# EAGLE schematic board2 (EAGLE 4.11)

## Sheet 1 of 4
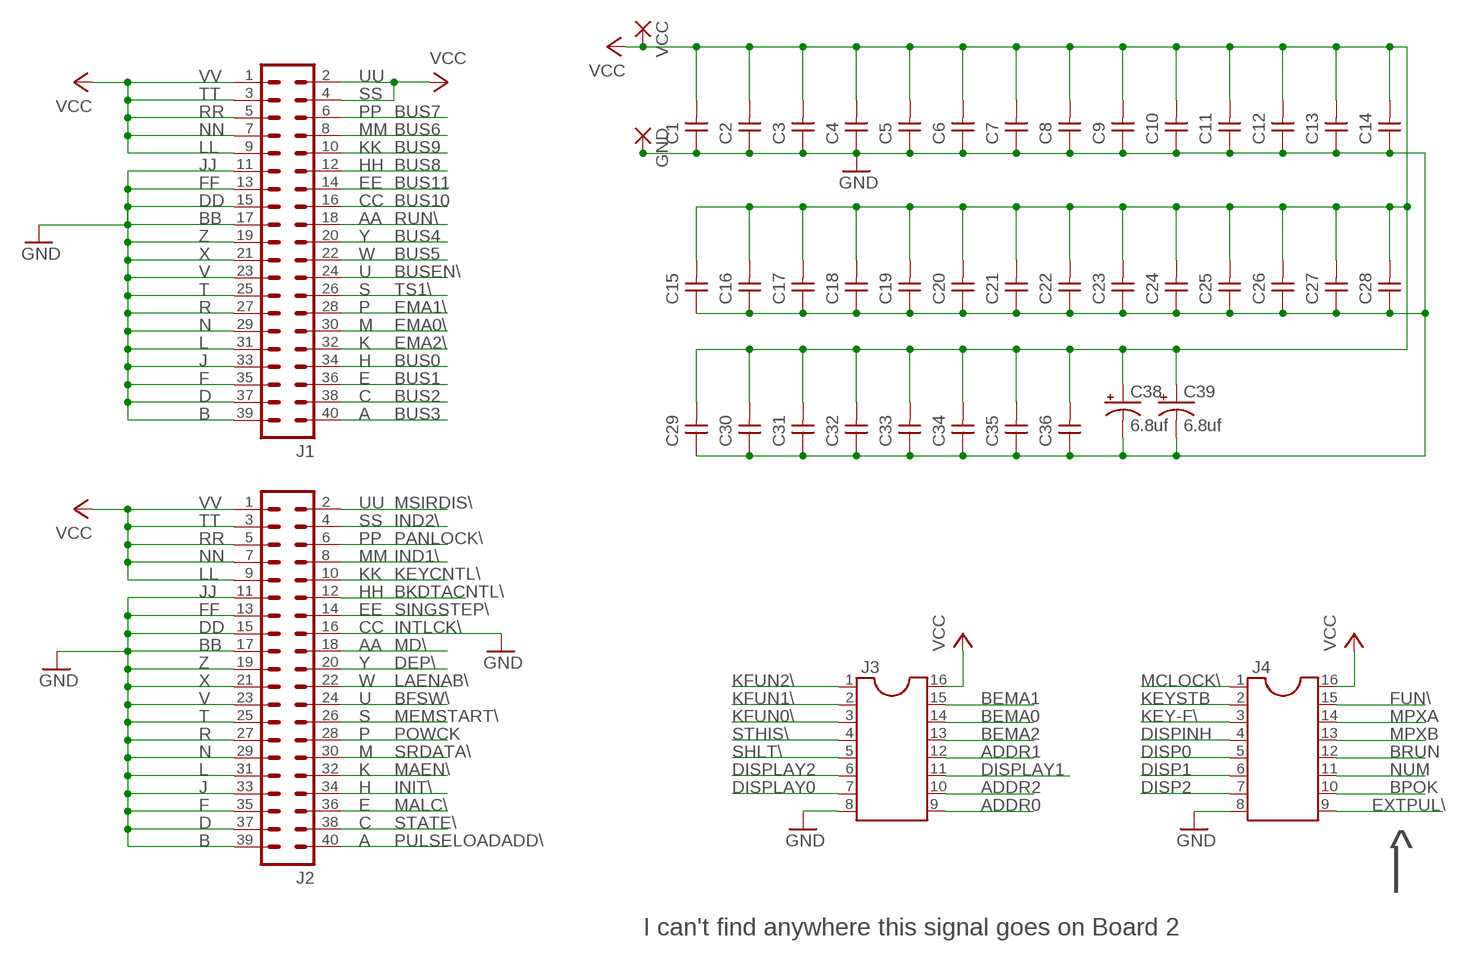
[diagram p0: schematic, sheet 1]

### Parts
C1  CAPNP-5  [C-5]
C2  CAPNP-5  [C-5]
C3  CAPNP-5  [C-5]
C4  CAPNP-5  [C-5]
C5  CAPNP-5  [C-5]
C6  CAPNP-5  [C-5]
C7  CAPNP-5  [C-5]
C8  CAPNP-5  [C-5]
C9  CAPNP-5  [C-5]
C10  CAPNP-5  [C-5]
C11  CAPNP-5  [C-5]
C12  CAPNP-5  [C-5]
C13  CAPNP-5  [C-5]
C14  CAPNP-5  [C-5]
C15  CAPNP-5  [C-5]
C16  CAPNP-5  [C-5]
C17  CAPNP-5  [C-5]
C18  CAPNP-5  [C-5]
C19  CAPNP-5  [C-5]
C20  CAPNP-5  [C-5]
C21  CAPNP-5  [C-5]
C22  CAPNP-5  [C-5]
C23  CAPNP-5  [C-5]
C24  CAPNP-5  [C-5]
C25  CAPNP-5  [C-5]
C26  CAPNP-5  [C-5]
C27  CAPNP-5  [C-5]
C28  CAPNP-5  [C-5]
C29  CAPNP-5  [C-5]
C30  CAPNP-5  [C-5]
C31  CAPNP-5  [C-5]
C32  CAPNP-5  [C-5]
C33  CAPNP-5  [C-5]
C34  CAPNP-5  [C-5]
C35  CAPNP-5  [C-5]
C36  CAPNP-5  [C-5]
C38  6.8uf  CPOL-USE15-5AXIAL  [E15-5]
C39  6.8uf  CPOL-USE15-5AXIAL  [E15-5]
GND  3,81/1,4  [3,81/1,4]
J1  40H  [40H]
J2  40H  [40H]
J3  DIL16S  [SOCKED-16]
J4  DIL16S  [SOCKED-16]
VCC  3,81/1,4  [3,81/1,4]

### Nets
ADDR0: J3.9 ; also sheet 2
ADDR1: J3.12 ; also sheet 2
ADDR2: J3.10 ; also sheet 2
BEMA0: J3.14 ; also sheet 4
BEMA1: J3.15 ; also sheet 4
BEMA2: J3.13 ; also sheet 4
BFSW\: J2.24 ; also sheet 4
BKDTACNTL\: J2.12 ; also sheet 4
BPOK: J4.10 ; also sheet 2,3,4
BRUN: J4.12 ; also sheet 3,4
BUS0: J1.34 ; also sheet 2
BUS1: J1.36 ; also sheet 2
BUS2: J1.38 ; also sheet 2
BUS3: J1.40 ; also sheet 2
BUS4: J1.20 ; also sheet 2
BUS5: J1.22 ; also sheet 2
BUS6: J1.8 ; also sheet 2
BUS7: J1.6 ; also sheet 2
BUS8: J1.12 ; also sheet 2
BUS9: J1.10 ; also sheet 2
BUS10: J1.16 ; also sheet 2
BUS11: J1.14 ; also sheet 2
BUSEN\: J1.24 ; also sheet 4
DEP\: J2.20 ; also sheet 4
DISP0: J4.5 ; also sheet 4
DISP1: J4.6 ; also sheet 4
DISP2: J4.7 ; also sheet 4
DISPINH: J4.4 ; also sheet 3,4
DISPLAY0: J3.7 ; also sheet 2
DISPLAY1: J3.11 ; also sheet 2
DISPLAY2: J3.6 ; also sheet 2
EMA0\: J1.30 ; also sheet 4
EMA1\: J1.28 ; also sheet 4
EMA2\: J1.32 ; also sheet 4
EXTPUL\: J4.9
FUN\: J4.15 ; also sheet 3,4
GND [Supply]: C1.1 C2.1 C3.1 C4.1 C5.1 C6.1 C7.1 C8.1 C9.1 C10.1 C11.1 C12.1 C13.1 C14.1 C15.1 C16.1 C17.1 C18.1 C19.1 C20.1 C21.1 C22.1 C23.1 C24.1 C25.1 C26.1 C27.1 C28.1 C29.1 C30.1 C31.1 C32.1 C33.1 C34.1 C35.1 C36.1 C38.- C39.- GND.1(P) J1.11 J1.13 J1.15 J1.17 J1.19 J1.21 J1.23 J1.25 J1.27 J1.29 J1.31 J1.33 J1.35 J1.37 J1.39 J2.11 J2.13 J2.15 J2.16 J2.17 J2.19 J2.21 J2.23 J2.25 J2.27 J2.29 J2.31 J2.33 J2.35 J2.37 J2.39 J3.8 J4.8 ; also sheet 2,3,4
IND1\: J2.8 ; also sheet 4
IND2\: J2.4 ; also sheet 4
INIT\: J2.34 ; also sheet 4
KEY-F\: J4.3 ; also sheet 4
KEYCNTL\: J2.10 ; also sheet 4
KEYSTB: J4.2 ; also sheet 3
KFUN0\: J3.3 ; also sheet 2,4
KFUN1\: J3.2 ; also sheet 2,4
KFUN2\: J3.1 ; also sheet 2,4
LAENAB\: J2.22 ; also sheet 4
MAEN\: J2.32 ; also sheet 4
MALC\: J2.36 ; also sheet 4
MCLOCK\: J4.1 ; also sheet 3
MD\: J2.18 ; also sheet 4
MEMSTART\: J2.26 ; also sheet 4
MPXA: J4.14 ; also sheet 2
MPXB: J4.13 ; also sheet 2
MSIRDIS\: J2.2 ; also sheet 4
NUM: J4.11 ; also sheet 3
PANLOCK\: J2.6 ; also sheet 4
POWCK: J2.28 ; also sheet 4
PULSELOADADD\: J2.40 ; also sheet 4
RUN\: J1.18 ; also sheet 3
SHLT\: J3.5 ; also sheet 4
SINGSTEP\: J2.14 ; also sheet 4
SRDATA\: J2.30 ; also sheet 3,4
STATE\: J2.38 ; also sheet 4
STHIS\: J3.4 ; also sheet 4
TS1\: J1.26 ; also sheet 3,4
VCC [Supply]: C1.2 C2.2 C3.2 C4.2 C5.2 C6.2 C7.2 C8.2 C9.2 C10.2 C11.2 C12.2 C13.2 C14.2 C15.2 C16.2 C17.2 C18.2 C19.2 C20.2 C21.2 C22.2 C23.2 C24.2 C25.2 C26.2 C27.2 C28.2 C29.2 C30.2 C31.2 C32.2 C33.2 C34.2 C35.2 C36.2 C38.+ C39.+ J1.1 J1.2 J1.3 J1.4 J1.5 J1.7 J1.9 J2.1 J2.3 J2.5 J2.7 J2.9 J3.16 J4.16 VCC.1(P) ; also sheet 2,3,4

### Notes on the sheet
- VV | UU
- TT | SS
- RR | PP
- NN | MM
- LL | KK
- JJ | HH
- FF | EE
- DD | CC
- BB | AA
- Z | Y
- X | W
- V | U
- T | S
- R | P
- N | M
- L | K
- J | H
- F | E
- D | C
- B | A
- VV | UU
- TT | SS
- RR | PP
- NN | MM
- LL | KK
- JJ | HH
- FF | EE
- DD | CC | INTLCK\
- BB | AA
- Z | Y
- X | W
- V | U
- T | S
- R | P
- N | M
- L | K
- J | H
- F | E
- D | C
- B | A
- ^
- |
- I can't find anywhere this signal goes on Board 2

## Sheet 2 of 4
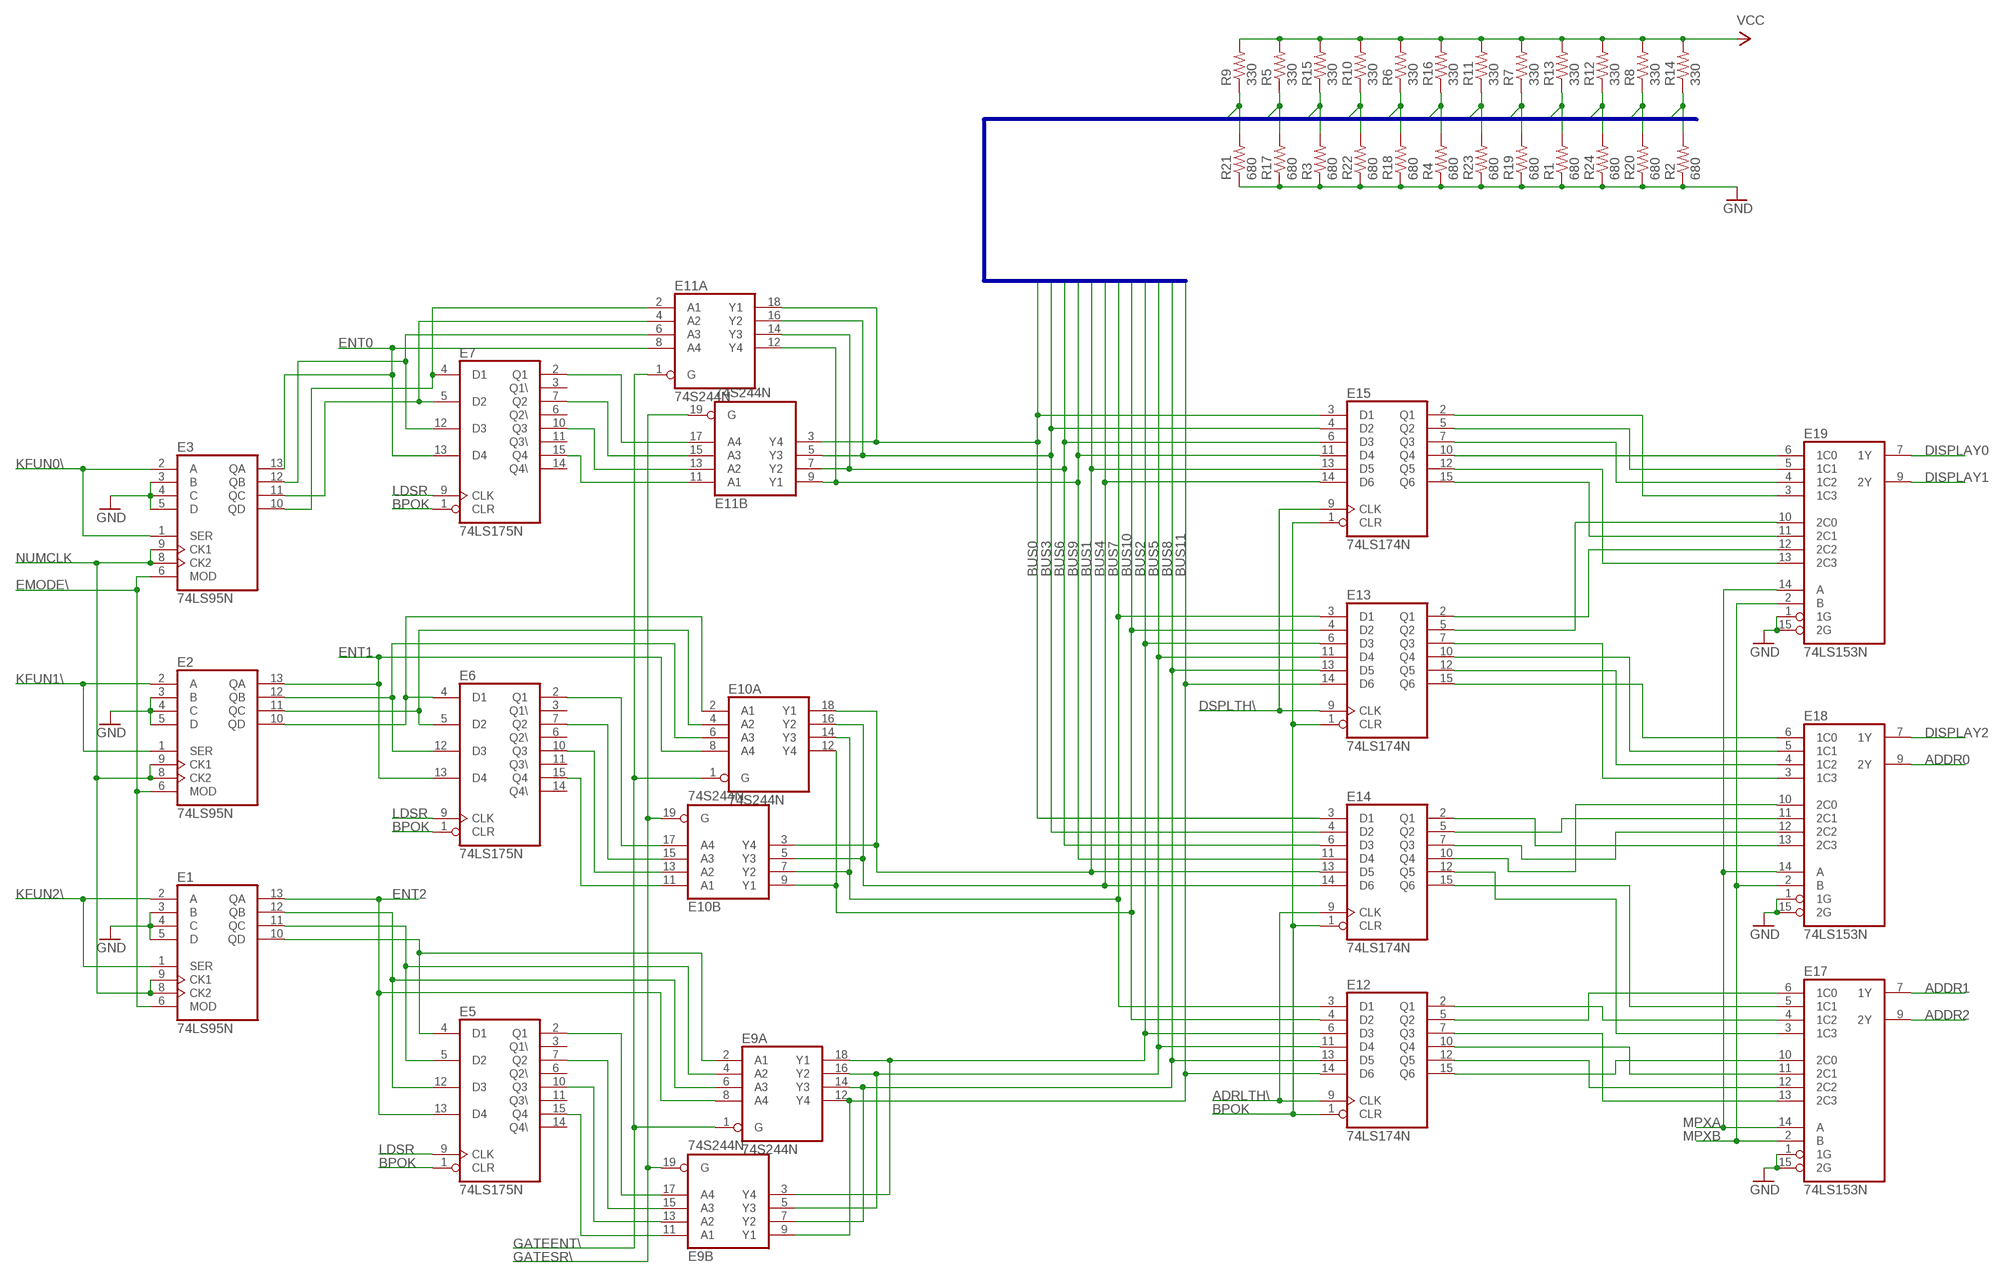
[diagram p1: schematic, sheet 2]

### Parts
E1  74LS95N  [DIL14]
E2  74LS95N  [DIL14]
E3  74LS95N  [DIL14]
E5  74LS175N  [DIL16]
E6  74LS175N  [DIL16]
E7  74LS175N  [DIL16]
E9  74S244N  [DIL20]
E10  74S244N  [DIL20]
E11  74S244N  [DIL20]
E12  74LS174N  [DIL16]
E13  74LS174N  [DIL16]
E14  74LS174N  [DIL16]
E15  74LS174N  [DIL16]
E17  74LS153N  [DIL16]
E18  74LS153N  [DIL16]
E19  74LS153N  [DIL16]
R1  680  R-US_0207/10  [0207/10]
R2  680  R-US_0207/10  [0207/10]
R3  680  R-US_0207/10  [0207/10]
R4  680  R-US_0207/10  [0207/10]
R5  330  R-US_0207/10  [0207/10]
R6  330  R-US_0207/10  [0207/10]
R7  330  R-US_0207/10  [0207/10]
R8  330  R-US_0207/10  [0207/10]
R9  330  R-US_0207/10  [0207/10]
R10  330  R-US_0207/10  [0207/10]
R11  330  R-US_0207/10  [0207/10]
R12  330  R-US_0207/10  [0207/10]
R13  330  R-US_0207/10  [0207/10]
R14  330  R-US_0207/10  [0207/10]
R15  330  R-US_0207/10  [0207/10]
R16  330  R-US_0207/10  [0207/10]
R17  680  R-US_0207/10  [0207/10]
R18  680  R-US_0207/10  [0207/10]
R19  680  R-US_0207/10  [0207/10]
R20  680  R-US_0207/10  [0207/10]
R21  680  R-US_0207/10  [0207/10]
R22  680  R-US_0207/10  [0207/10]
R23  680  R-US_0207/10  [0207/10]
R24  680  R-US_0207/10  [0207/10]

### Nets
ADDR0: E18.9(2Y) ; also sheet 1
ADDR1: E17.7(1Y) ; also sheet 1
ADDR2: E17.9(2Y) ; also sheet 1
ADRLTH\: E12.9(CLK) E14.9(CLK) ; also sheet 3
BPOK: E5.1(CLR) E6.1(CLR) E7.1(CLR) E12.1(CLR) E13.1(CLR) E14.1(CLR) E15.1(CLR) ; also sheet 1,3,4
BUS0: E11.3(B:Y4) E11.18(A:Y1) E14.3(D1) E15.3(D1) R9.1 R21.2 ; also sheet 1
BUS1: E10.3(B:Y4) E10.18(A:Y1) E14.13(D5) E15.13(D5) R5.1 R17.2 ; also sheet 1
BUS2: E9.3(B:Y4) E9.18(A:Y1) E12.6(D3) E13.6(D3) R3.2 R15.1 ; also sheet 1
BUS3: E11.5(B:Y3) E11.16(A:Y2) E14.4(D2) E15.4(D2) R10.1 R22.2 ; also sheet 1
BUS4: E10.5(B:Y3) E10.16(A:Y2) E14.14(D6) E15.14(D6) R6.1 R18.2 ; also sheet 1
BUS5: E9.5(B:Y3) E9.16(A:Y2) E12.11(D4) E13.11(D4) R4.2 R16.1 ; also sheet 1
BUS6: E11.7(B:Y2) E11.14(A:Y3) E14.6(D3) E15.6(D3) R11.1 R23.2 ; also sheet 1
BUS7: E10.7(B:Y2) E10.14(A:Y3) E12.3(D1) E13.3(D1) R7.1 R19.2 ; also sheet 1
BUS8: E9.7(B:Y2) E9.14(A:Y3) E12.13(D5) E13.13(D5) R1.2 R12.1 R13.1 R24.2 ; also sheet 1
BUS9: E11.9(B:Y1) E11.12(A:Y4) E14.11(D4) E15.11(D4) ; also sheet 1
BUS10: E10.9(B:Y1) E10.12(A:Y4) E12.4(D2) E13.4(D2) R8.1 R20.2 ; also sheet 1
BUS11: E9.9(B:Y1) E9.12(A:Y4) E12.14(D6) E13.14(D6) R2.2 R14.1 ; also sheet 1
DISPLAY0: E19.7(1Y) ; also sheet 1
DISPLAY1: E19.9(2Y) ; also sheet 1
DISPLAY2: E18.7(1Y) ; also sheet 1
DSPLTH\: E13.9(CLK) E15.9(CLK) ; also sheet 3
EMODE\: E1.6(MOD) E2.6(MOD) E3.6(MOD) ; also sheet 3
ENT0: E3.13(QA) E7.13(D4) E11.8(A:A4) ; also sheet 4
ENT1: E2.13(QA) E6.13(D4) E10.8(A:A4) ; also sheet 4
ENT2: E1.13(QA) E5.13(D4) E9.8(A:A4) ; also sheet 4
GATEENT\: E9.1(A:G) E10.1(A:G) E11.1(A:G) ; also sheet 3,4
GATESR\: E9.19(B:G) E10.19(B:G) E11.19(B:G) ; also sheet 4
GND [Supply]: E1.3(B) E1.4(C) E1.5(D) E2.3(B) E2.4(C) E2.5(D) E3.3(B) E3.4(C) E3.5(D) E17.1(1G) E17.15(2G) E18.1(1G) E18.15(2G) E19.1(1G) E19.15(2G) R1.1 R2.1 R3.1 R4.1 R17.1 R18.1 R19.1 R20.1 R21.1 R22.1 R23.1 R24.1 ; also sheet 1,3,4
KFUN0\: E3.1(SER) E3.2(A) ; also sheet 1,4
KFUN1\: E2.1(SER) E2.2(A) ; also sheet 1,4
KFUN2\: E1.1(SER) E1.2(A) ; also sheet 1,4
LDSR: E5.9(CLK) E6.9(CLK) E7.9(CLK) ; also sheet 4
MPXA: E17.14(A) E18.14(A) E19.14(A) ; also sheet 1
MPXB: E17.2(B) E18.2(B) E19.2(B) ; also sheet 1
N$1: E2.12(QB) E6.12(D3) E10.6(A:A3)
N$2: E1.12(QB) E5.12(D3) E9.6(A:A3)
N$3: E1.10(QD) E5.4(D1) E9.2(A:A1)
N$4: E1.11(QC) E5.5(D2) E9.4(A:A2)
N$5: E2.10(QD) E6.4(D1) E10.2(A:A1)
N$6: E2.11(QC) E6.5(D2) E10.4(A:A2)
N$7: E3.12(QB) E7.12(D3) E11.6(A:A3)
N$8: E3.10(QD) E7.4(D1) E11.2(A:A1)
N$9: E3.11(QC) E7.5(D2) E11.4(A:A2)
N$10: E15.2(Q1) E19.3(1C3)
N$11: E15.5(Q2) E19.5(1C1)
N$12: E15.7(Q3) E19.4(1C2)
N$13: E15.10(Q4) E19.6(1C0)
N$14: E15.12(Q5) E19.13(2C3)
N$15: E15.15(Q6) E19.11(2C1)
N$16: E13.2(Q1) E19.12(2C2)
N$17: E13.5(Q2) E19.10(2C0)
N$18: E13.7(Q3) E18.3(1C3)
N$19: E13.10(Q4) E18.5(1C1)
N$20: E13.12(Q5) E18.4(1C2)
N$21: E13.15(Q6) E18.6(1C0)
N$22: E14.2(Q1) E18.13(2C3)
N$23: E14.5(Q2) E18.11(2C1)
N$24: E14.7(Q3) E18.12(2C2)
N$25: E14.10(Q4) E18.10(2C0)
N$26: E12.15(Q6) E17.10(2C0)
N$27: E12.12(Q5) E17.12(2C2)
N$28: E12.10(Q4) E17.11(2C1)
N$29: E12.7(Q3) E17.13(2C3)
N$30: E14.15(Q6) E17.5(1C1)
N$31: E14.12(Q5) E17.3(1C3)
N$32: E12.2(Q1) E17.4(1C2)
N$33: E12.5(Q2) E17.6(1C0)
N$63: E7.15(Q4) E11.11(B:A1)
N$64: E7.10(Q3) E11.13(B:A2)
N$65: E7.7(Q2) E11.15(B:A3)
N$66: E7.2(Q1) E11.17(B:A4)
N$79: E6.15(Q4) E10.11(B:A1)
N$80: E6.10(Q3) E10.13(B:A2)
N$81: E6.7(Q2) E10.15(B:A3)
N$82: E6.2(Q1) E10.17(B:A4)
N$83: E5.15(Q4) E9.11(B:A1)
N$84: E5.10(Q3) E9.13(B:A2)
N$85: E5.2(Q1) E9.17(B:A4)
N$86: E5.7(Q2) E9.15(B:A3)
NUMCLK: E1.8(CK2) E1.9(CK1) E2.8(CK2) E2.9(CK1) E3.8(CK2) E3.9(CK1) ; also sheet 3
VCC [Supply]: R5.2 R6.2 R7.2 R8.2 R9.2 R10.2 R11.2 R12.2 R13.2 R14.2 R15.2 R16.2 ; also sheet 1,3,4
Unconnected: E5.3(Q1\) E5.6(Q2\) E5.11(Q3\) E5.14(Q4\) E6.3(Q1\) E6.6(Q2\) E6.11(Q3\) E6.14(Q4\) E7.3(Q1\) E7.6(Q2\) E7.11(Q3\) E7.14(Q4\)

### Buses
BUS[0..11]

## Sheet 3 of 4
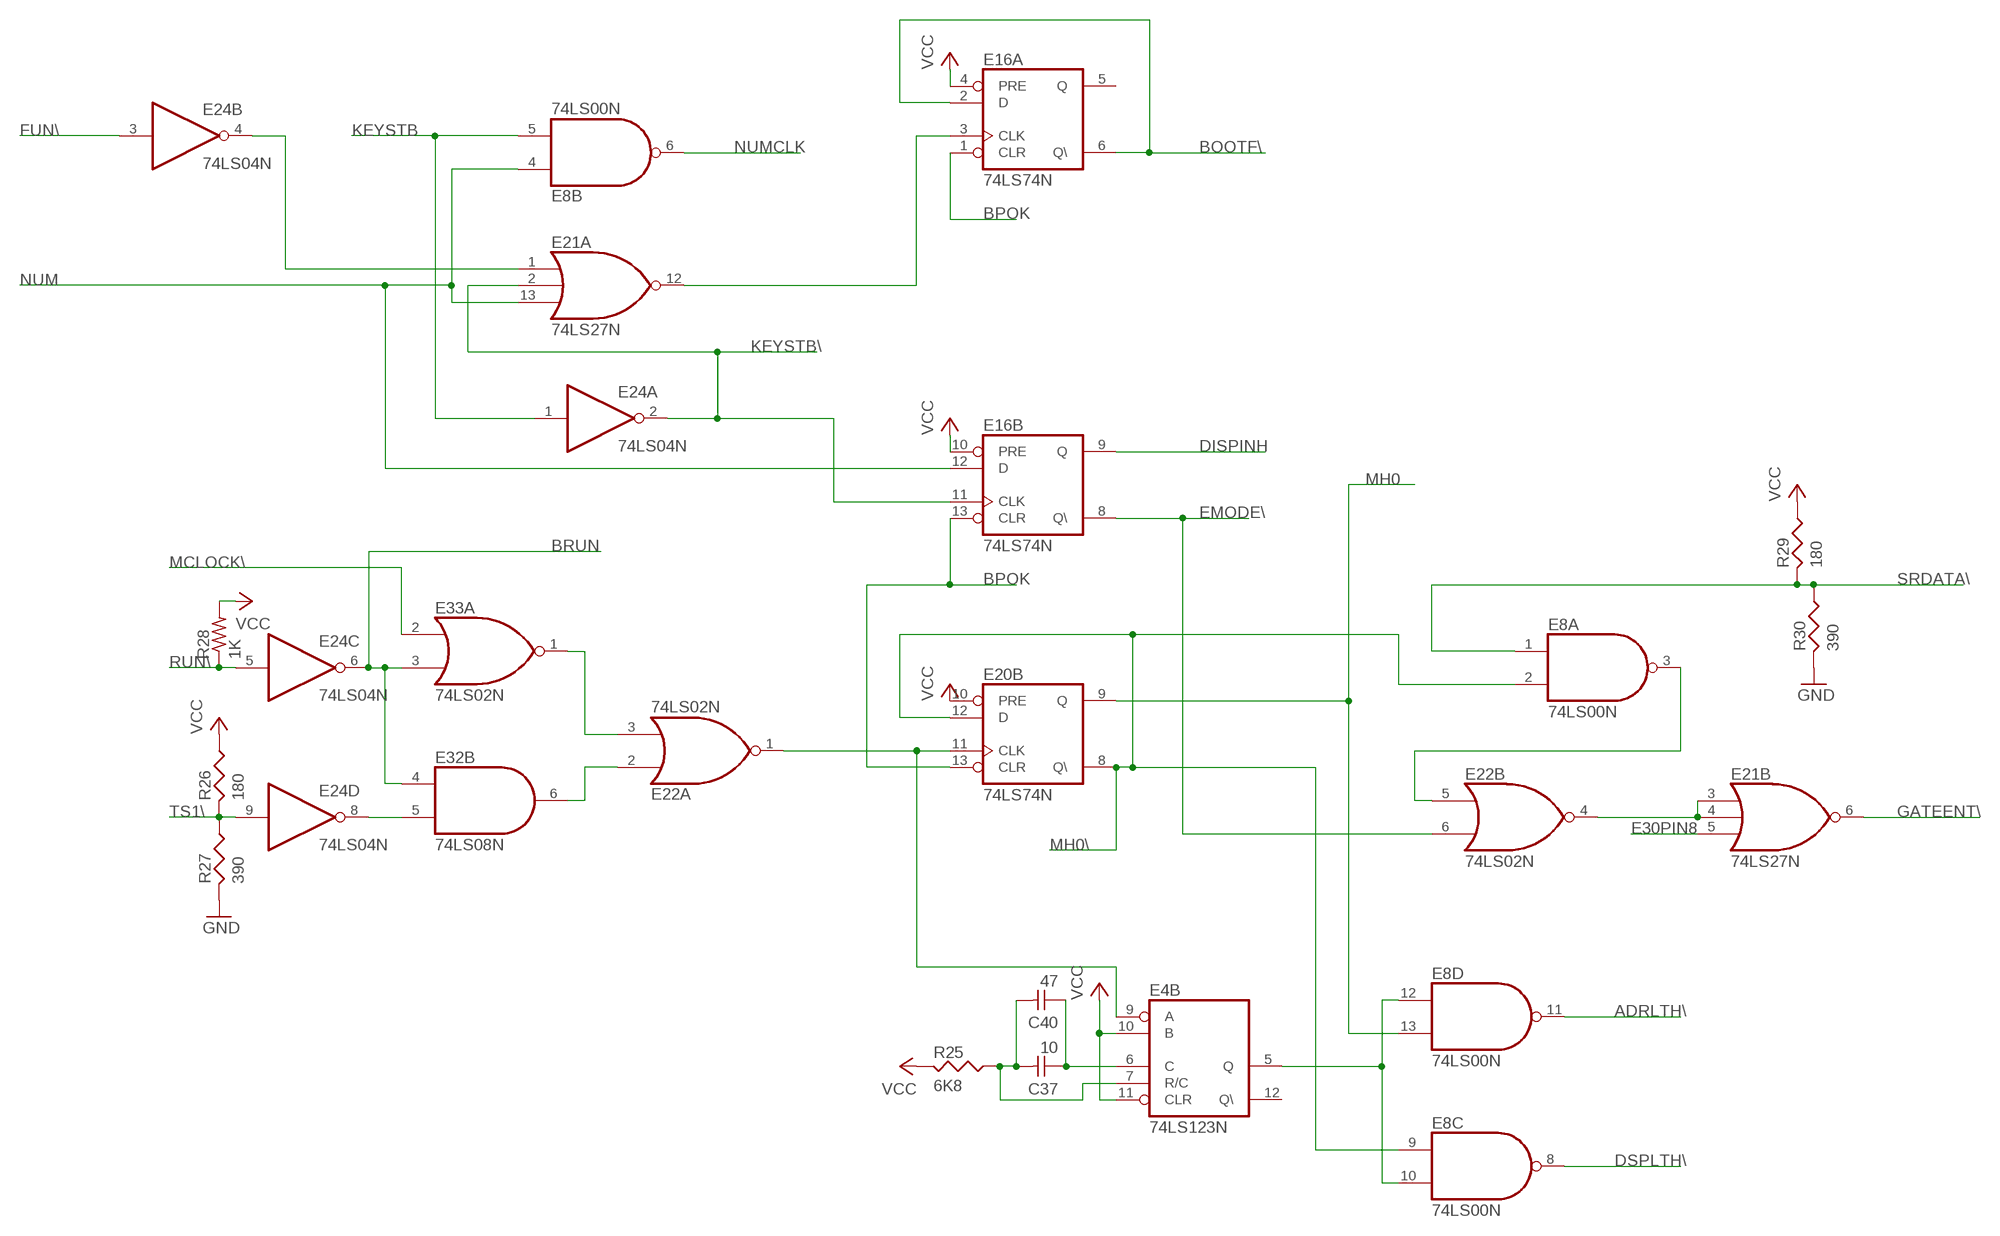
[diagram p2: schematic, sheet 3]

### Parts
C37  10  CAPNP-5  [C-5]
C40  47  CAPNP-5  [C-5]
E4  74LS123N  [DIL16]
E8  74LS00N  [DIL14]
E16  74LS74N  [DIL14]
E20  74LS74N  [DIL14]
E21  74LS27N  [DIL14]
E22  74LS02N  [DIL14]
E24  74LS04N  [DIL14]
E32  74LS08N  [DIL14]
E33  74LS02N  [DIL14]
R25  6K8  RESUS-10  [R-10]
R26  180  RESUS-10  [R-10]
R27  390  RESUS-10  [R-10]
R28  1K  R-US_0207/10  [0207/10]
R29  180  RESUS-10  [R-10]
R30  390  RESUS-10  [R-10]

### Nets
ADRLTH\: E8.11(D:O) ; also sheet 2
BOOTF\: E16.2(A:D) E16.6(A:Q\) ; also sheet 4
BPOK: E16.1(A:CLR) E16.13(B:CLR) E20.13(B:CLR) ; also sheet 1,2,4
BRUN: E24.6(C:O) E32.4(B:I0) E33.3(A:I1) ; also sheet 1,4
DISPINH: E16.9(B:Q) ; also sheet 1,4
DSPLTH\: E8.8(C:O) ; also sheet 2
E30PIN8: E21.5(B:I2) ; also sheet 4
EMODE\: E16.8(B:Q\) E22.6(B:I1) ; also sheet 2
FUN\: E24.3(B:I) ; also sheet 1,4
GATEENT\: E21.6(B:O) ; also sheet 2,4
GND [Supply]: R27.2 R30.2 ; also sheet 1,2,4
KEYSTB: E8.5(B:I1) E24.1(A:I) ; also sheet 1
KEYSTB\: E16.11(B:CLK) E21.2(A:I1) E24.2(A:O) ; also sheet 4
MCLOCK\: E33.2(A:I0) ; also sheet 1
MH0: E8.13(D:I1) E20.9(B:Q) ; also sheet 4
MH0\: E8.2(A:I1) E8.9(C:I0) E20.8(B:Q\) E20.12(B:D) ; also sheet 4
N$34: E16.3(A:CLK) E21.12(A:O)
N$35: E21.1(A:I0) E24.4(B:O)
N$38: E8.3(A:O) E22.5(B:I0)
N$39: E22.3(A:I1) E33.1(A:O)
N$40: E22.2(A:I0) E32.6(B:O)
N$41: E4.9(B:A) E20.11(B:CLK) E22.1(A:O)
N$44: E24.8(D:O) E32.5(B:I1)
N$52: E21.3(B:I0) E21.4(B:I1) E22.4(B:O)
N$75: E4.5(B:Q) E8.10(C:I1) E8.12(D:I0)
N$88: C37.1 C40.1 E4.6(B:C)
N$89: C37.2 C40.2 E4.7(B:R/C) R25.1
NUM: E8.4(B:I0) E16.12(B:D) E21.13(A:I2) ; also sheet 1
NUMCLK: E8.6(B:O) ; also sheet 2
RUN\: E24.5(C:I) R28.1 ; also sheet 1
SRDATA\: E8.1(A:I0) R29.2 R30.1 ; also sheet 1,4
TS1\: E24.9(D:I) R26.2 R27.1 ; also sheet 1,4
VCC [Supply]: E4.10(B:B) E4.11(B:CLR) E16.4(A:PRE) E16.10(B:PRE) E20.10(B:PRE) R25.2 R26.1 R28.2 R29.1 ; also sheet 1,2,4
Unconnected: E4.1(A:A) E4.2(A:B) E4.3(A:CLR) E4.4(A:Q\) E4.12(B:Q\) E4.13(A:Q) E4.14(A:C) E4.15(A:R/C) E16.5(A:Q)

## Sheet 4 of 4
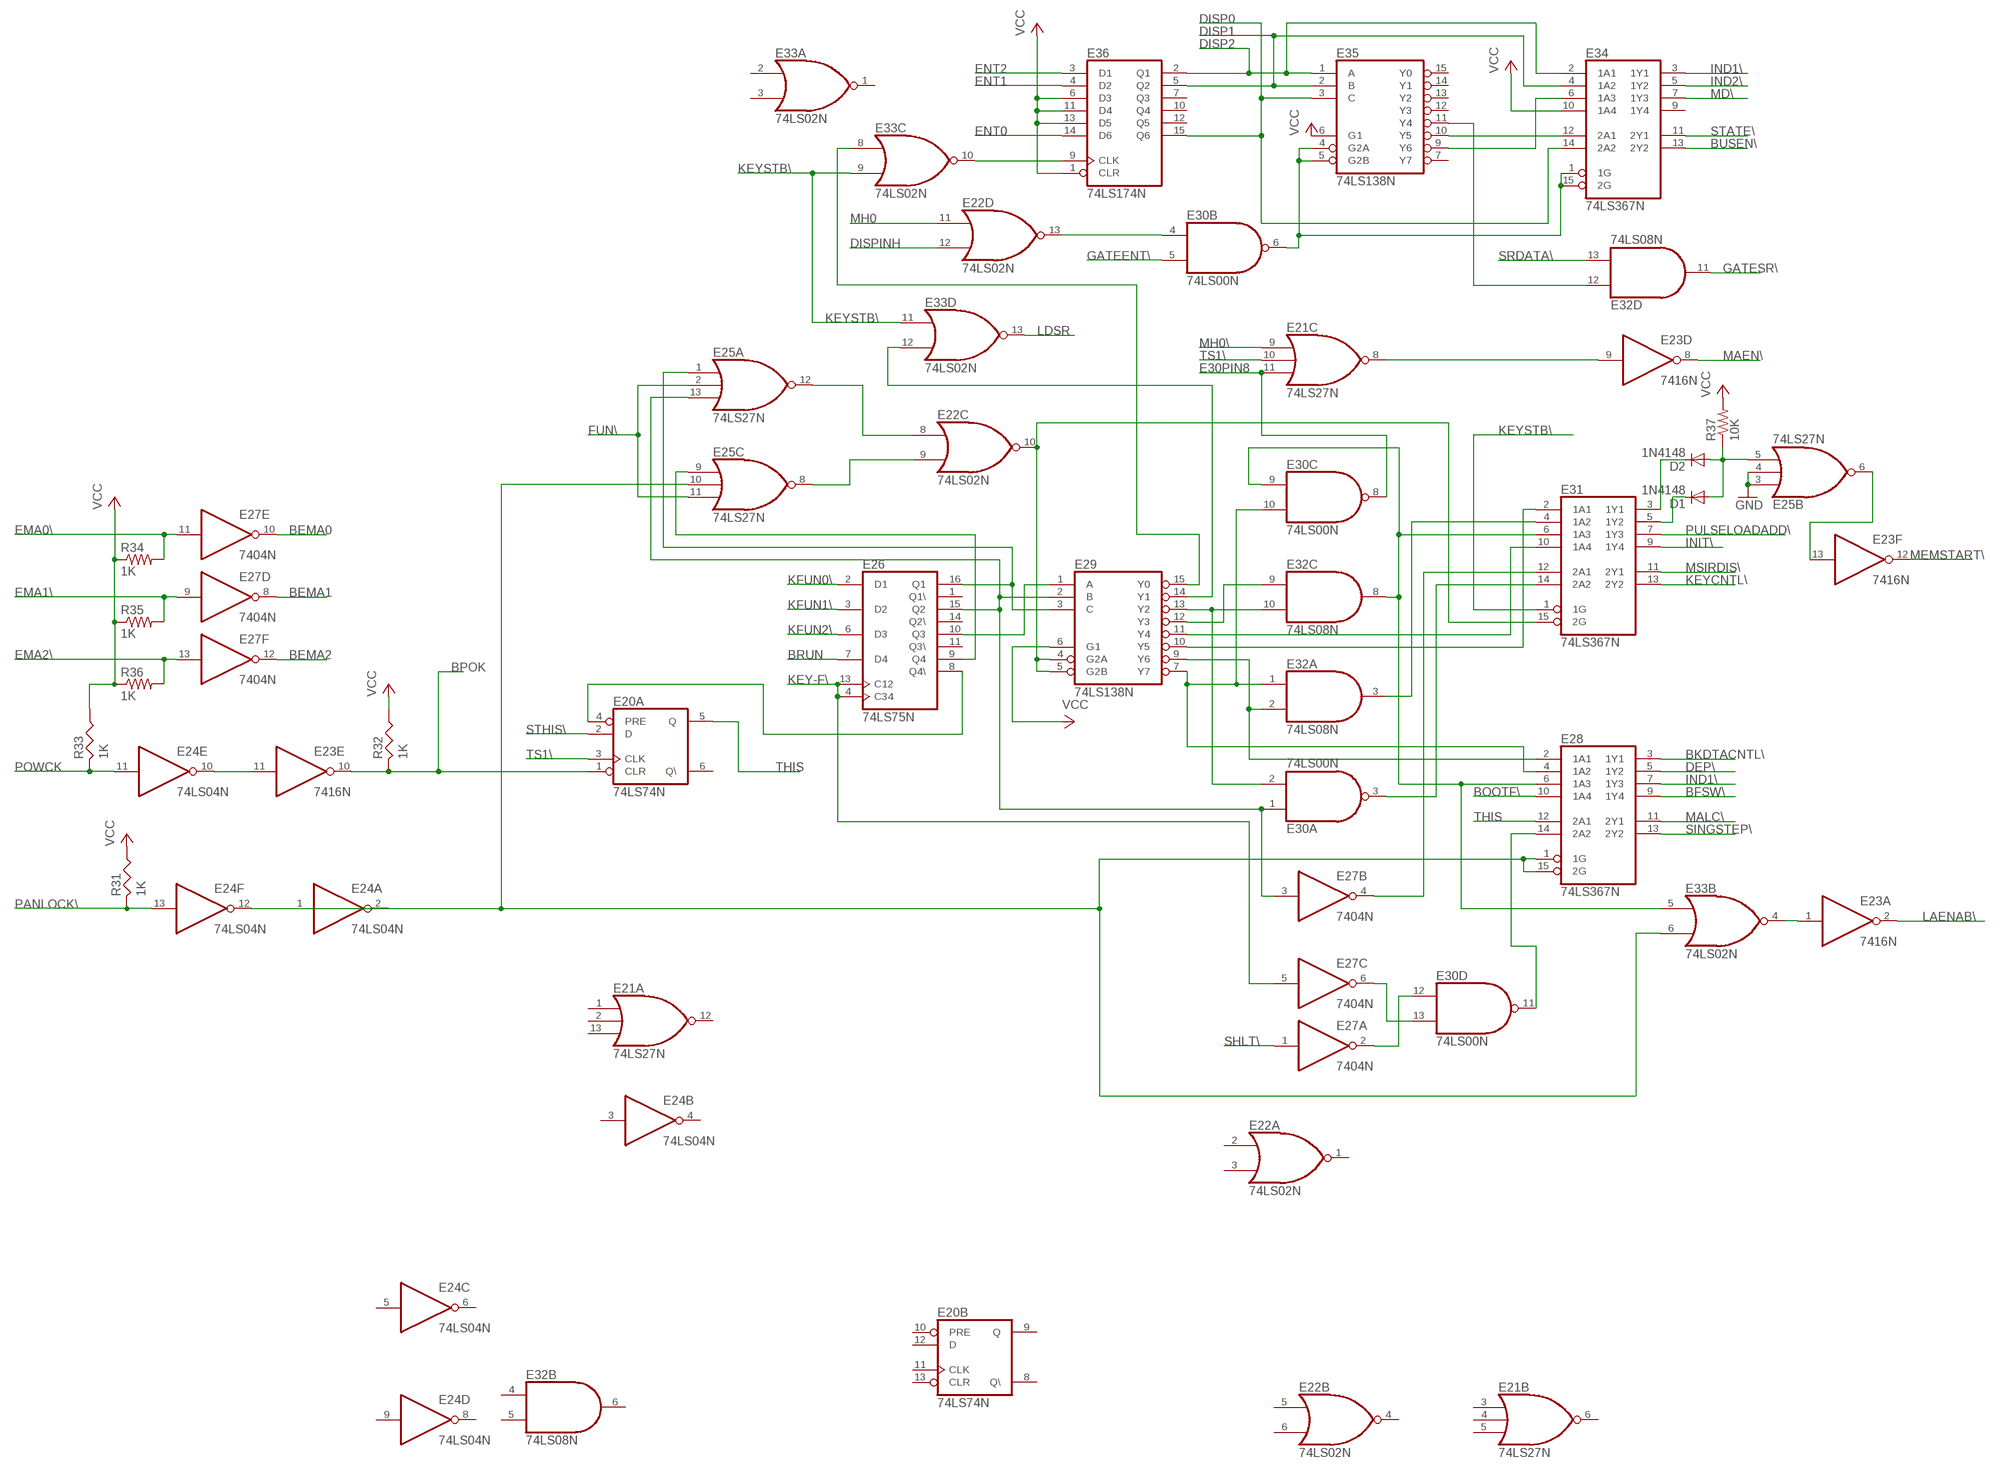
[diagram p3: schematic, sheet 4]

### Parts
D1  1N4148  [DO35-10]
D2  1N4148  [DO35-10]
E23  7416N  [DIL14]
E25  74LS27N  [DIL14]
E26  74LS75N  [DIL16]
E27  7404N  [DIL14]
E28  74LS367N  74367N  [DIL16]
E29  74LS138N  [DIL16]
E30  74LS00N  [DIL14]
E31  74LS367N  74367N  [DIL16]
E34  74LS367N  74367N  [DIL16]
E35  74LS138N  [DIL16]
E36  74LS174N  [DIL16]
R31  1K  RESUS-10  [R-10]
R32  1K  RESUS-10  [R-10]
R33  1K  RESUS-10  [R-10]
R34  1K  R-US_0207/10  [0207/10]
R35  1K  R-US_0207/10  [0207/10]
R36  1K  R-US_0207/10  [0207/10]
R37  10K  R-US_0207/10  [0207/10]

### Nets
BEMA0: E27.10(E:O) ; also sheet 1
BEMA1: E27.8(D:O) ; also sheet 1
BEMA2: E27.12(F:O) ; also sheet 1
BFSW\: E28.9(1Y4) ; also sheet 1
BKDTACNTL\: E28.3(1Y1) ; also sheet 1
BOOTF\: E28.10(1A4) ; also sheet 3
BPOK: E20.1(A:CLR) E23.10(E:O) R32.2 ; also sheet 1,2,3
BRUN: E26.7(D4) ; also sheet 1,3
BUSEN\: E34.13(2Y2) ; also sheet 1
DEP\: E28.5(1Y2) ; also sheet 1
DISP0: E34.14(2A2) E35.3(C) E36.15(Q6) ; also sheet 1
DISP1: E34.4(1A2) E35.2(B) E36.5(Q2) ; also sheet 1
DISP2: E34.2(1A1) E35.1(A) E36.2(Q1) ; also sheet 1
DISPINH: E22.12(D:I1) ; also sheet 1,3
E30PIN8: E21.11(C:I2) E30.8(C:O) ; also sheet 3
E35-Y4: E32.12(D:I0) E35.11(Y4)
EMA0\: E27.11(E:I) R34.2 ; also sheet 1
EMA1\: E27.9(D:I) R35.2 ; also sheet 1
EMA2\: E27.13(F:I) R36.2 ; also sheet 1
ENT0: E36.14(D6) ; also sheet 2
ENT1: E36.4(D2) ; also sheet 2
ENT2: E36.3(D1) ; also sheet 2
FUN\: E25.2(A:I1) E25.11(C:I2) ; also sheet 1,3
GATEENT\: E30.5(B:I1) ; also sheet 2,3
GATESR\: E32.11(D:O) ; also sheet 2
GND [Supply]: E25.3(B:I0) E25.4(B:I1) ; also sheet 1,2,3
IND1\: E28.7(1Y3) E34.3(1Y1) ; also sheet 1
IND2\: E34.5(1Y2) ; also sheet 1
INIT\: E31.9(1Y4) ; also sheet 1
KEY-F\: E26.4(C34) E26.13(C12) E27.5(C:I) ; also sheet 1
KEYCNTL\: E31.13(2Y2) ; also sheet 1
KEYSTB\: E31.1(1G) E33.9(C:I1) E33.11(D:I0) ; also sheet 3
KFUN0\: E26.2(D1) ; also sheet 1,2
KFUN1\: E26.3(D2) ; also sheet 1,2
KFUN2\: E26.6(D3) ; also sheet 1,2
LAENAB\: E23.2(A:O) ; also sheet 1
LDSR: E33.13(D:O) ; also sheet 2
MAEN\: E23.8(D:O) ; also sheet 1
MALC\: E28.11(2Y1) ; also sheet 1
MD\: E34.7(1Y3) ; also sheet 1
MEMSTART\: E23.12(F:O) ; also sheet 1
MH0: E22.11(D:I0) ; also sheet 3
MH0\: E21.9(C:I0) ; also sheet 3
MSIRDIS\: E31.11(2Y1) ; also sheet 1
N$36: E22.10(C:O) E29.4(G2A) E29.5(G2B) E31.15(2G)
N$37: E22.13(D:O) E30.4(B:I0)
N$42: E22.8(C:I0) E25.12(A:O)
N$43: D1.C E31.5(1Y2)
N$45: D2.C E31.3(1Y1)
N$46: E33.10(C:O) E36.9(CLK)
N$47: E23.11(E:I) E24.10(E:O)
N$48: E29.15(Y0) E33.8(C:I0)
N$49: E26.10(Q3) E29.1(A)
N$50: E25.13(A:I2) E26.15(Q2) E27.3(B:I) E29.2(B) E30.1(A:I0)
N$51: E25.1(A:I0) E26.16(Q1) E29.3(C)
N$53: E22.9(C:I1) E25.8(C:O)
N$54: D1.A D2.A E25.5(B:I2) R37.1
N$55: E28.4(1A2) E29.7(Y7) E30.10(C:I1) E32.1(A:I0)
N$56: E28.2(1A1) E29.9(Y6) E32.2(A:I1)
N$57: E29.10(Y5) E31.2(1A1)
N$58: E29.11(Y4) E31.10(1A4)
N$59: E29.12(Y3) E32.9(C:I0)
N$60: E29.13(Y2) E30.2(A:I1) E32.10(C:I1)
N$61: E29.14(Y1) E33.12(D:I1)
N$62: E23.1(A:I) E33.4(B:O)
N$67: E27.6(C:O) E30.13(D:I1)
N$68: E28.14(2A2) E30.11(D:O)
N$69: E31.4(1A2) E32.3(A:O)
N$70: E30.6(B:O) E34.1(1G) E34.15(2G) E35.4(G2A) E35.5(G2B)
N$71: E28.6(1A3) E30.9(C:I0) E31.6(1A3) E32.8(C:O) E33.5(B:I0)
N$72: E34.12(2A1) E35.10(Y5)
N$73: E34.6(1A3) E35.9(Y6)
N$74: E27.4(B:O) E31.12(2A1)
N$76: E30.3(A:O) E31.14(2A2)
N$77: E27.2(A:O) E30.12(D:I0)
N$78: E23.13(F:I) E25.6(B:O)
N$87: E21.8(C:O) E23.9(D:I)
N$93: E20.4(A:PRE) E26.8(Q4\)
N$94: E25.9(C:I0) E26.9(Q4)
PANLOCK: E24.12(F:O) E25.10(C:I1) E28.1(1G) E28.15(2G) E33.6(B:I1)
PANLOCK\: E24.13(F:I) R31.2 ; also sheet 1
POWCK: E24.11(E:I) R33.2 ; also sheet 1
PULSELOADADD\: E31.7(1Y3) ; also sheet 1
SHLT\: E27.1(A:I) ; also sheet 1
SINGSTEP\: E28.13(2Y2) ; also sheet 1
SRDATA\: E32.13(D:I1) ; also sheet 1,3
STATE\: E34.11(2Y1) ; also sheet 1
STHIS\: E20.2(A:D) ; also sheet 1
THIS: E20.5(A:Q) E28.12(2A1)
TS1\: E20.3(A:CLK) E21.10(C:I1) ; also sheet 1,3
VCC [Supply]: E29.6(G1) E34.10(1A4) E35.6(G1) E36.1(CLR) E36.6(D3) E36.11(D4) E36.13(D5) R31.1 R32.1 R33.1 R34.1 R35.1 R36.1 R37.2 ; also sheet 1,2,3
Unconnected: E20.6(A:Q\) E23.3(B:I) E23.4(B:O) E23.5(C:I) E23.6(C:O) E26.1(Q1\) E26.11(Q3\) E26.14(Q2\) E34.9(1Y4) E35.7(Y7) E35.12(Y3) E35.13(Y2) E35.14(Y1) E35.15(Y0) E36.7(Q3) E36.10(Q4) E36.12(Q5)

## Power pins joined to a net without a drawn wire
GND: E1.7(GND) E2.7(GND) E3.7(GND) E4.8(P:GND) E5.8(GND) E6.8(GND) E7.8(GND) E8.7(P:GND) E9.10(P:GND) E10.10(P:GND) E11.10(P:GND) E12.8(GND) E13.8(GND) E14.8(GND) E15.8(GND) E16.7(P:GND) E17.8(GND) E18.8(GND) E19.8(GND) E20.7(P:GND) E21.7(P:GND) E22.7(P:GND) E23.7(P:GND) E24.7(P:GND) E25.7(P:GND) E26.12(GND) E27.7(P:GND) E28.8(GND) E29.8(GND) E30.7(P:GND) E31.8(GND) E32.7(P:GND) E33.7(P:GND) E34.8(GND) E35.8(GND) E36.8(GND)
VCC: E1.14(VCC) E2.14(VCC) E3.14(VCC) E4.16(P:VCC) E5.16(VCC) E6.16(VCC) E7.16(VCC) E8.14(P:VCC) E9.20(P:VCC) E10.20(P:VCC) E11.20(P:VCC) E12.16(VCC) E13.16(VCC) E14.16(VCC) E15.16(VCC) E16.14(P:VCC) E17.16(VCC) E18.16(VCC) E19.16(VCC) E20.14(P:VCC) E21.14(P:VCC) E22.14(P:VCC) E23.14(P:VCC) E24.14(P:VCC) E25.14(P:VCC) E26.5(VCC) E27.14(P:VCC) E28.16(VCC) E29.16(VCC) E30.14(P:VCC) E31.16(VCC) E32.14(P:VCC) E33.14(P:VCC) E34.16(VCC) E35.16(VCC) E36.16(VCC)

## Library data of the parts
C1-C37 C40 = discrete:CAPNP-5
C38 C39 = rcl:CPOL-US: POLARIZED CAPACITOR, American symbol
D1 D2 = diode:1N4148: DIODE
E1-E3 = 74xx-us:74*95: 4-bit parallel access SHIFT REGISTER
E4 = 74xx-us:74*123: Retriggerable monostable MULTIVIBRATOR
E5-E7 = 74xx-us:74*175: Qadruple D type FLIP FLOP, clear
E8 E30 = 74xx-us:74*00: Quad 2-input NAND gate
E9-E11 = 74xx-us:74*244: Octal BUFFER and LINE DRIVER, 3-state
E12-E15 E36 = 74xx-us:74*174: Hex D type FLIP FLOP, clear
E16 E20 = 74xx-us:74*74: Dual D type positive edge triggered FLIP FLOP, preset and clear
E17-E19 = 74xx-us:74*153: Dual 4-line to 1-line data SELECTOR/MULTIPLEXER
E21 E25 = 74xx-us:74*27: Triple 3-input NOR gate
E22 E33 = 74xx-us:74*02: Quad 2-input NOR gate
E23 = 74xx-us:74*16: Hex INVERTER, open collector, high-voltage
E24 E27 = 74xx-us:74*04: Hex INVERTER
E26 = 74xx-us:74*75: 4-bit bistable LATCH
E28 E31 E34 = 74xx-us:74*367: Hex BUS DRIVER, 3-state
E29 E35 = 74xx-us:74*138: 3-line to 8-line DECODER/DEMULTIPLEXER
E32 = 74xx-us:74*08: Quad 2-input AND gate
GND VCC = wirepad:3,81/1,4: THROUGH-HOLE PAD
J1 J2 = con-harting-h:40H: CONNECTOR
J3 J4 = ic-package:DIL16: Dual In Line
R1-R24 R28 R34-R37 = rcl:R-US_: RESISTOR, American symbol
R25-R27 R29-R33 = discrete:RESUS-10

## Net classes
1 Supply: width 0.508 mm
